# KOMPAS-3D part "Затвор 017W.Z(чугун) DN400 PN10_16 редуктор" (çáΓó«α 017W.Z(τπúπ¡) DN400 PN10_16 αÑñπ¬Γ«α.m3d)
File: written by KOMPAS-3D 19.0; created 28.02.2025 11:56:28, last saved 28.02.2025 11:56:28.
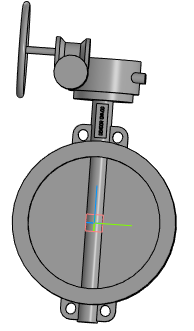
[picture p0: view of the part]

Document properties: Автор: Евгений; Полное имя файла: Затвор 017W.Z(чугун) DN400 PN10_16 редуктор.a3d

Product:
- Part/product: Затвор 017W.Z(чугун) DN400 PN10_16 редуктор
    Масса: 127.276

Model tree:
1. Операция без истории:1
